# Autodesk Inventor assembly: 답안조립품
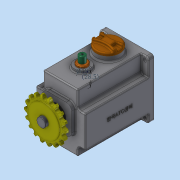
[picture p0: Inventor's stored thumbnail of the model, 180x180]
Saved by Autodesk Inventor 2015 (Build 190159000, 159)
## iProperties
Created: 2017-12
Part Number: 답안조립품
Document SubType Name: Assembly
Designer: SCD-A03
Author: SCD-A03
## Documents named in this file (17)
- C:\Users\SCD-A03\Desktop\371207V1032\답안조립품.iam
- C:\Users\SCD-A03\Desktop\371207V1032\본체.ipt
- C:\Users\SCD-A03\Desktop\371207V1032\멈춤나사 M3x8.ipt
- C:\Users\SCD-A03\Desktop\371207V1032\메인축.ipt
- C:\Users\SCD-A03\Desktop\371207V1032\베어링 608.ipt
- C:\Users\SCD-A03\Desktop\371207V1032\베어링 6003.ipt
- C:\Users\SCD-A03\Desktop\371207V1032\볼트 M4 x 10.ipt
- C:\Users\SCD-A03\Desktop\371207V1032\부시.ipt
- C:\Users\SCD-A03\Desktop\371207V1032\상부 캡.ipt
- C:\Users\SCD-A03\Desktop\371207V1032\서브축.ipt
- C:\Users\SCD-A03\Desktop\371207V1032\스프로킷.ipt
- C:\Users\SCD-A03\Desktop\371207V1032\슬라이더.ipt
- C:\Users\SCD-A03\Desktop\371207V1032\오일 실 8 22 7.ipt
- C:\Users\SCD-A03\Desktop\371207V1032\오일 실 17 32 8.ipt
- C:\Users\SCD-A03\Desktop\371207V1032\커버.ipt
- C:\Users\SCD-A03\Desktop\371207V1032\키 5 x 5 x 18.ipt
- C:\Users\SCD-A03\Desktop\371207V1032\가변스프링.ipt
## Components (1 placed, 1 different names)
1. 가변스프링:1
